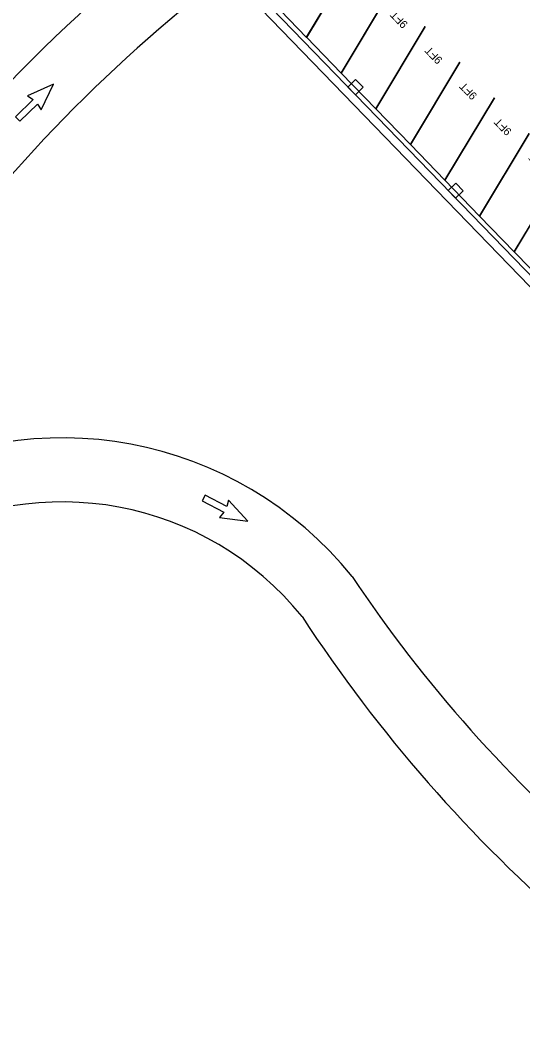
# Model space of a CAD drawing. Extents: x 468143 to 491361, y 1438528 to 1468730.
# Drawn here: x 490134.6 to 490228.7, y 1467224 to 1467411.7 of the extents above; entities that cross this region are included whole.
import ezdxf

# ---------------------------------------------------------------- set-up
doc = ezdxf.new("R2010")
doc.units = 0
doc.layers.add('Default', color=7, linetype='Continuous')
doc.layers.add('Xreference_dp', color=7, linetype='Continuous')

# ---------------------------------------------------------------- blocks, each defined once
blk = doc.blocks.new('arrow-thru')
at = {"layer": 'Default'}
blk.add_lwpolyline([(14.99997, 0), (28.999942, 0), (28.999942, 54.99989), (43.999912, 51.999896), (21.999956, 111.999776), (0, 51.999896), (14.99997, 54.99989)], close=True, dxfattribs=at)
blk = doc.blocks.new('Col 24x24')
at = {"layer": 'Default'}
blk.add_lwpolyline([(-11.999976, -11.999976), (-11.999976, 11.999976), (11.999976, 11.999976), (11.999976, -11.999976), (-11.999976, -11.999976)], dxfattribs=at)
blk.add_lwpolyline([(-11.999976, -11.999976), (11.999976, -11.999976), (11.999976, 11.999976), (-11.999976, 11.999976)], close=True, dxfattribs=at)
blk = doc.blocks.new('STALL 9FT-75D')
at = {"layer": 'Default'}
for p, q in [((0, 0), (111.8, 0)), ((111.8, 0), (167.7, -208.6))]:
    blk.add_line(p, q, dxfattribs=at)
blk.add_lwpolyline([(55.9, -208.6), (0, 0)], dxfattribs=at)
blk.add_text('9FT', height=18, dxfattribs=at).set_placement((86.4, -185.9))

msp = doc.modelspace()

# ---------------------------------------------------------------- linework, layer by layer
at = {"layer": 'Xreference_dp'}
msp.add_line((490322.87, 1467268.03), (490139.28, 1467457.72), dxfattribs=at)
msp.add_line((490322.87, 1467268.03), (490139.28, 1467457.72), dxfattribs=at)
msp.add_lwpolyline([(490342.06, 1467246.02), (490137.16, 1467457.76), (490471.58, 1467781.33), (490516.38, 1467735.04), (490628.6, 1467843.61), (490790.28, 1467676.55), (490385, 1467284.32)], close=True, dxfattribs=at)
msp.add_lwpolyline([(490342.06, 1467246.02), (490137.16, 1467457.76), (490471.58, 1467781.33), (490516.38, 1467735.04), (490628.6, 1467843.61), (490790.28, 1467676.55), (490385, 1467284.32)], close=True, dxfattribs=at)
for centre, radius, start, end in [((490349.3, 1467191.71), 300.58, 124.6193, 161.3764), ((490349.3, 1467191.71), 300.58, 124.6193, 161.3764), ((490349.3, 1467191.71), 288.58, 127.0804, 161.3764), ((490349.3, 1467191.71), 288.58, 127.0804, 161.3764), ((490142.5, 1467263.84), 69.61, 38.8288, 201.1598), ((490142.5, 1467263.84), 69.61, 38.8288, 201.1598), ((490142.5, 1467263.84), 57.61, 38.8288, 201.1598), ((490142.5, 1467263.84), 57.61, 38.8288, 201.1598), ((490415.4, 1467453.37), 262.86, 213.709, 229.5742), ((490415.4, 1467453.37), 262.86, 213.709, 229.5742), ((488571.3, 1469355.06), 2785.78, 306.41751, 312.53817), ((490421.96, 1467453.34), 280.27, 213.179, 229.1707), ((490421.96, 1467453.34), 280.27, 213.179, 229.1707)]:
    msp.add_arc(centre, radius, start, end, dxfattribs=at)

# ---------------------------------------------------------------- block references
for name, p, xscale, yscale, rotation in [('STALL 9FT-75D', (490188.22, 1467408.47), 0.0833307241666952, 0.08333072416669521, 134.05706724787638), ('STALL 9FT-75D', (490188.22, 1467408.47), 0.0833307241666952, 0.08333072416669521, 134.05706724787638), ('STALL 9FT-75D', (490194.7, 1467401.78), 0.0833307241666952, 0.08333072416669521, 134.05706724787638), ('STALL 9FT-75D', (490194.7, 1467401.78), 0.0833307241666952, 0.08333072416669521, 134.05706724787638), ('STALL 9FT-75D', (490201.17, 1467395.08), 0.0833307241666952, 0.08333072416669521, 134.05706724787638), ('STALL 9FT-75D', (490201.17, 1467395.08), 0.0833307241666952, 0.08333072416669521, 134.05706724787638), ('STALL 9FT-75D', (490207.65, 1467388.39), 0.0833307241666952, 0.08333072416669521, 134.05706724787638), ('STALL 9FT-75D', (490207.65, 1467388.39), 0.0833307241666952, 0.08333072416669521, 134.05706724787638), ('STALL 9FT-75D', (490214.13, 1467381.69), 0.0833307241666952, 0.08333072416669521, 134.05706724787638), ('STALL 9FT-75D', (490214.13, 1467381.69), 0.0833307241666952, 0.08333072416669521, 134.05706724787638), ('arrow-thru', (490132.86, 1467394.51), 0.08333072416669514, 0.08333072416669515, -45.942932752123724), ('arrow-thru', (490132.86, 1467394.51), 0.08333072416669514, 0.08333072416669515, -45.942932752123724), ('Col 24x24', (490197.37, 1467399.14), 0.0833307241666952, 0.0833307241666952, 44.062944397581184), ('Col 24x24', (490197.37, 1467399.14), 0.0833307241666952, 0.0833307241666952, 44.062944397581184), ('Col 24x24', (490197.37, 1467399.14), 0.0833307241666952, 0.0833307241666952, 44.062944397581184), ('Col 24x24', (490197.37, 1467399.14), 0.0833307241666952, 0.0833307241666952, 44.062944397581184), ('STALL 9FT-75D', (490220.61, 1467375), 0.0833307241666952, 0.08333072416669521, 134.05706724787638), ('STALL 9FT-75D', (490220.61, 1467375), 0.0833307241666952, 0.08333072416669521, 134.05706724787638), ('STALL 9FT-75D', (490227.09, 1467368.3), 0.0833307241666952, 0.08333072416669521, 134.05706724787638), ('STALL 9FT-75D', (490227.09, 1467368.3), 0.0833307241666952, 0.08333072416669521, 134.05706724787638), ('STALL 9FT-75D', (490233.57, 1467361.6), 0.0833307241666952, 0.08333072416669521, 134.05706724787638), ('STALL 9FT-75D', (490233.57, 1467361.6), 0.0833307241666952, 0.08333072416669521, 134.05706724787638), ('Col 24x24', (490216.15, 1467379.74), 0.0833307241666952, 0.0833307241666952, 44.062944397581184), ('Col 24x24', (490216.15, 1467379.74), 0.0833307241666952, 0.0833307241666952, 44.062944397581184), ('Col 24x24', (490216.15, 1467379.74), 0.0833307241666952, 0.0833307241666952, 44.062944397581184), ('Col 24x24', (490216.15, 1467379.74), 0.0833307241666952, 0.0833307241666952, 44.062944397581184), ('arrow-thru', (490169.8, 1467323.81), 0.08333072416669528, 0.08333072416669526, -117.8965140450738), ('arrow-thru', (490169.8, 1467323.81), 0.08333072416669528, 0.08333072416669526, -117.8965140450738)]:
    msp.add_blockref(name, p, dxfattribs=dict(at, xscale=xscale, yscale=yscale, rotation=rotation))

doc.saveas('drawing.dxf')
